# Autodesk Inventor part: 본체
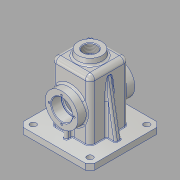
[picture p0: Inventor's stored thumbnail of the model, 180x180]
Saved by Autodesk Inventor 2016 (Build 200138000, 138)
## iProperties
Created: 2018-10
Part Number: 본체
Material: 알루미늄 6061
Document SubType Name: Modeling
Designer: user
Density: 2.7 g/cm^3
Appearance: 알루미늄 - 평지
Mass: 794.217 g
Surface Area: 899.433 cm^2
Volume: 294.154 cm^3
Author: user
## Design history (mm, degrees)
sketch "스케치1"
  geometry: L1 (60, 60)-(-60, 60); L2 (-60, 60)-(-60, -60); L3 (-60, -60)-(60, -60); L4 (60, -60)-(60, 60); L5 (60, 60)-(-60, -60); L6 (-60, 60)-(60, -60); 1 further point
  constraints: 12 end point, 2 midpoint, 2 parallel, 1 horizontal, 1 perpendicular
  dimensions: "d0" = 120 distance of L3.end L2.end; "d1" = 120 distance of L2.end L1.end
extrude "돌출1" new body sketch "스케치1" distance "d2" = 10; taper "d3" = 0 deg
sketch "스케치2"
  geometry: L1 (32.5, -32.5)-(-32.5, -32.5); L2 (-32.5, -32.5)-(-32.5, 32.5); L3 (-32.5, 32.5)-(32.5, 32.5); L4 (32.5, 32.5)-(32.5, -32.5); L5 (32.5, -32.5)-(-32.5, 32.5); L6 (-32.5, -32.5)-(32.5, 32.5); 1 further point
  constraints: 12 end point, 2 midpoint, 2 parallel, 1 horizontal, 1 perpendicular
  dimensions: "d4" = 65 distance of L2.end L3.end; "d5" = 65 distance of L1.end L2.end
extrude "돌출2" join sketch "스케치2" distance "d6" = 100; taper "d7" = 0 deg
sketch "스케치3"
  geometry: L1 (-27.5, 27.5)-(27.5, 27.5); L2 (27.5, 27.5)-(27.5, -27.5); L3 (27.5, -27.5)-(-27.5, -27.5); L4 (-27.5, -27.5)-(-27.5, 27.5); L5 (-27.5, 27.5)-(27.5, -27.5); L6 (27.5, 27.5)-(-27.5, -27.5); 1 further point
  constraints: 12 end point, 2 midpoint, 2 parallel, 1 horizontal, 1 perpendicular
  dimensions: "d8" = 55 distance of L2.end L3.end; "d9" = 55 distance of L1.end L2.end
extrude "돌출3" cut sketch "스케치3" distance "d10" = 105; taper "d11" = 0 deg
sketch "스케치4"
  geometry: L1 (-27.5, -10)-(92.5, -10) reference; C1 r 27.5 at (32.5, 45); 2 further points
  constraints: 1 centre point, 1 midpoint, 1 vertical alignment
  dimensions: "d12" = 55 diameter of C1; "d13" = 55 distance from line of L1 C1.centre
extrude "돌출4" join sketch "스케치4" distance "d14" = 15; taper "d15" = 0 deg
sketch "스케치5"
  geometry: C1 r 27.5 at (0, 0) reference; C2 r 17.5 at (0, 0); 1 further point
  constraints: 1 centre point, 1 coincident
  dimensions: "d16" = 35 diameter of C2
extrude "돌출5" cut sketch "스케치5" distance "d17" = 17; taper "d18" = 0 deg
sketch "스케치6"
  geometry: L1 (60, -55)-(-60, -55) reference; L2 (32.5, 55)-(-32.5, 55) reference; C1 r 15 at (0, 0); 2 further points
  constraints: 1 centre point, 1 midpoint, 1 vertical alignment
  dimensions: "d19" = 30 diameter of C1; "d20" = 55 distance from line of L1 C1.centre
extrude "돌출6" cut sketch "스케치6" distance "d21" = 17; taper "d22" = 0 deg
sketch "스케치7" dims "d23" = 42
  geometry: C1 r 27.5 at (0, 0) reference; 3 further points
  constraints: 2 vertical alignment, 1 coincident, 2 other
hole "구멍1" sketch "스케치7" at (0, 21) diameter "d24" = 3.242; stored, may be unused: countersink angle "d28" = 90 deg, drill point angle "d30" = 118 deg; dims "d25" = 8, "d26" = 4, "d27" = 2, "d29" = 10
node "작업 평면1"
sketch "스케치9"
  geometry: C1 r 20 at (0, 0); 1 further point
  constraints: 1 centre point, 1 coincident
  dimensions: "d35" = 40 diameter of C1
extrude "돌출7" join sketch "스케치9" stored distance "d36" = 17; taper "d37" = 7 deg
sketch "스케치10"
  geometry: 2 further points
  constraints: 1 coincident
hole "구멍2" sketch "스케치10" at (0, 0) diameter "d38" = 22.835; stored, may be unused: countersink angle "d42" = 90 deg, drill point angle "d44" = 118 deg; dims "d39" = 50, "d40" = 4, "d41" = 2, "d43" = 59.3
sketch "스케치11"
  geometry: L1 (32.5, 10)-(32.5, 110) reference; L2 (60, 10)-(-60, 10) reference; L3 (48, 10)-(32.5, 97.905); L4 (60, 0)-(60, 10) reference; 1 further point
  constraints: 2 end point, 2 point on line
  dimensions: "d45" = 12 distance from line of L3.start L4; "d46" = 10 deg angle of L4 L3
extrude "돌출8" join sketch "스케치11" stored distance "d47" = 10; taper "d48" = 0 deg
sketch "스케치12"
  geometry: L1 (-3, -27.5)-(3, -27.5); L2 (3, -27.5)-(3, -42.5); L3 (3, -42.5)-(-3, -42.5); L4 (-3, -42.5)-(-3, -27.5); L5 (-27.5, -27.5)-(27.5, -27.5) reference; 2 further points
  constraints: 8 end point, 2 parallel, 1 collinear, 1 horizontal, 1 midpoint, 1 perpendicular, 1 vertical alignment
  dimensions: "d49" = 6 distance of L2.end L3.end; "d50" = 15 distance of L1.end L2.end
extrude "돌출9" join sketch "스케치12" distance "d51" = 20.75; taper "d52" = 0 deg
chamfer "모따기1" distance "d53" = 8; stored, may be unused: second distance "d54" = 2, angle "d55" = 45 deg
chamfer "모따기2" distance "d56" = 1; stored, may be unused: second distance "d57" = 2, angle "d58" = 45 deg
fillet "모깎기1" dims "d59" = 3
fillet "모깎기2" dims "d60" = 8
fillet "모깎기3" dims "d61" = 3
fillet "모깎기4" dims "d62" = 8, "d63" = 3
fillet "모깎기5" dims "d64" = 1
sketch "스케치13"
  geometry: L1 (-47.5, 47.5)-(47.5, 47.5); L2 (47.5, 47.5)-(47.5, -47.5); L3 (47.5, -47.5)-(-47.5, -47.5); L4 (-47.5, -47.5)-(-47.5, 47.5); L5 (-47.5, 47.5)-(47.5, -47.5); L6 (47.5, 47.5)-(-47.5, -47.5); C1 r 11.418 at (0, 0) reference; C2 r 5 at (47.5, 47.5); C3 r 5 at (-47.5, 47.5); C4 r 5 at (-47.5, -47.5); C5 r 5 at (47.5, -47.5); 1 further point
  constraints: 12 end point, 4 centre point, 4 coincident, 2 midpoint, 2 parallel, 1 horizontal, 1 perpendicular
  dimensions: "d65" = 95 distance of L2.end L3.end; "d66" = 95 distance of L1.end L2.end; "d67" = 10 diameter of C2; "d68" = 10 diameter of C3; "d69" = 10 diameter of C4; "d70" = 10 diameter of C5
extrude "돌출10" cut sketch "스케치13" stored distance "d71" = 20.75; taper "d72" = 0 deg
fillet "모깎기6" dims "d73" = 0.3
sketch "스케치14"
  geometry: L1 (-20, 65)-(20, 65) reference; L2 (-32.5, 47)-(-32.5, -44) reference; 2 further points
  constraints: 1 other
  dimensions: "d74" = 26 distance from line of point (0, 39) L1; "d75" = 32.5 distance from line of L2 point (0, 39)
extrude "돌출11" join sketch "스케치14" distance "d76" = 0.5; taper "d77" = 0 deg
node "솔리드1"
pattern_circular "원형 패턴1" dims angle "d32" = 360 deg
mirror "대칭1"
mirror "대칭2"
mirror "대칭3"
node "투영된 루프1"
